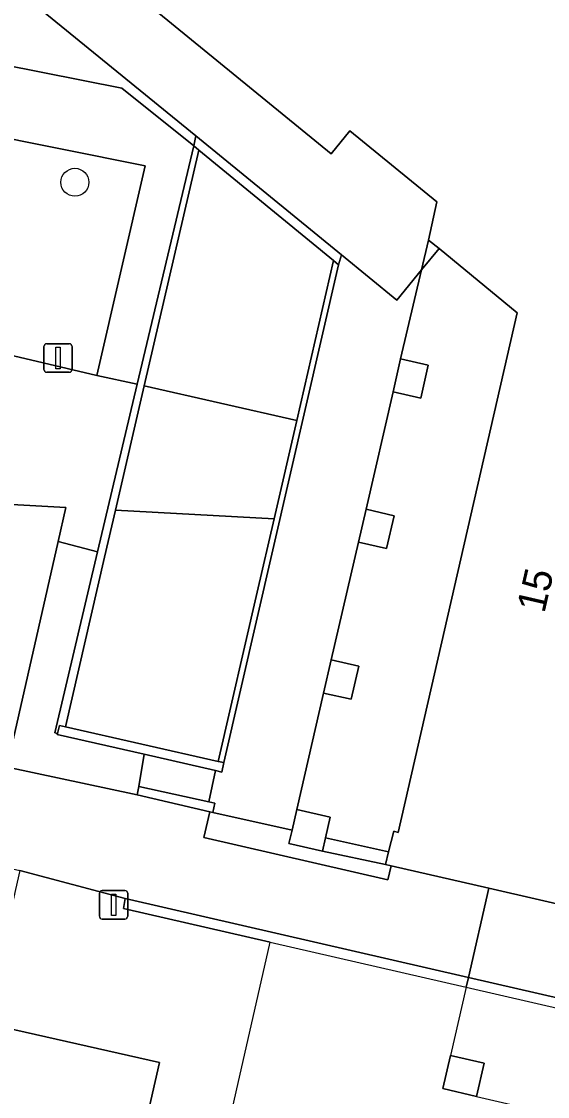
# Model space of a CAD drawing. Extents: x 161772 to 163126, y 383092 to 383917.
# Drawn here: x 161928.88 to 161947.28, y 383170.5 to 383208.09 of the extents above; entities that cross this region are included whole.
import ezdxf

# ---------------------------------------------------------------- set-up
doc = ezdxf.new("R2010")
doc.units = 0
for name, color, linetype in [('IMGEO_Boom', 7, 'Continuous'), ('IMGEO_Groenvoorziening', 7, 'Continuous'), ('IMGEO_Kademuur', 7, 'Continuous'), ('IMGEO_Lichtmast', 7, 'Continuous'), ('IMGEO_Pand', 7, 'Continuous'), ('IMGEO_Pand_nummerreeks', 7, 'Continuous'), ('IMGEO_Pand_overbouw', 7, 'Continuous'), ('IMGEO_Voetpad_gesloten', 7, 'Continuous'), ('IMGEO_Voetpad_op_trap', 7, 'Continuous'), ('IMGEO_Voetpad_open', 7, 'Continuous'), ('IMGEO_Waterloop', 7, 'Continuous')]:
    doc.layers.add(name, color=color, linetype=linetype)

msp = doc.modelspace()

# ---------------------------------------------------------------- linework, layer by layer
at = {"layer": 'IMGEO_Boom'}
msp.add_circle((161930.751, 383202.465), 0.489, dxfattribs=at)
at = {"layer": 'IMGEO_Groenvoorziening'}
for points in [[(161921.974, 383214.686), (161917.042, 383208.794), (161932.393, 383205.759), (161934.908, 383203.737), (161934.979, 383204.092)], [(161933.179, 383195.343), (161938.512, 383194.138), (161939.8, 383199.726), (161935.087, 383203.59)], [(161937.128, 383188.136), (161937.719, 383190.697), (161932.174, 383191), (161931.793, 383189.355), (161930.42, 383183.422), (161935.764, 383182.216)]]:
    msp.add_lwpolyline(points, close=True, dxfattribs=at)
for points in [[(161924.643, 383197.335), (161931.516, 383195.707), (161933.211, 383203.037), (161915.433, 383206.604), (161910.516, 383200.666), (161915.113, 383199.56)], [(161913.737, 383193.709), (161906.322, 383195.46), (161900.634, 383188.537), (161928.424, 383182.206), (161930.17, 383189.903), (161930.44, 383191.095), (161923.279, 383191.486)]]:
    msp.add_lwpolyline(points, dxfattribs=at)
at = {"layer": 'IMGEO_Kademuur'}
for points in [[(161932.509, 383177.423), (161932.457, 383177.072), (161937.581, 383175.895), (161944.437, 383174.32), (161944.517, 383174.665)], [(161944.517, 383174.665), (161944.437, 383174.32), (161982.458, 383165.585), (161982.538, 383165.93)]]:
    msp.add_lwpolyline(points, close=True, dxfattribs=at)
at = {"layer": 'IMGEO_Lichtmast'}
for p, q in [((161929.667, 383195.921), (161929.667, 383196.721)), ((161929.667, 383196.721), (161929.667, 383195.921)), ((161929.767, 383196.821), (161930.557, 383196.821)), ((161930.557, 383196.821), (161929.767, 383196.821)), ((161930.657, 383196.721), (161930.657, 383195.921)), ((161930.657, 383195.921), (161930.657, 383196.721)), ((161930.557, 383195.821), (161929.767, 383195.821)), ((161929.767, 383195.821), (161930.557, 383195.821)), ((161931.609, 383176.803), (161931.609, 383177.603)), ((161931.609, 383177.603), (161931.609, 383176.803)), ((161931.709, 383177.703), (161932.499, 383177.703)), ((161932.499, 383177.703), (161931.709, 383177.703)), ((161932.599, 383177.603), (161932.599, 383176.803)), ((161932.599, 383176.803), (161932.599, 383177.603)), ((161932.499, 383176.703), (161931.709, 383176.703)), ((161931.709, 383176.703), (161932.499, 383176.703))]:
    msp.add_line(p, q, dxfattribs=at)
for points in [[(161930.087, 383196.696), (161930.237, 383196.696), (161930.237, 383195.946), (161930.087, 383195.946), (161930.087, 383196.696)], [(161932.029, 383177.578), (161932.179, 383177.578), (161932.179, 383176.828), (161932.029, 383176.828), (161932.029, 383177.578)]]:
    msp.add_lwpolyline(points, dxfattribs=at)
for centre, start, end in [((161929.767, 383196.721), 90, 180), ((161929.767, 383196.721), 90, 180), ((161930.557, 383196.721), 0, 90), ((161930.557, 383196.721), 360, 90), ((161929.767, 383195.921), 180, 270), ((161929.767, 383195.921), 180, 270), ((161930.557, 383195.921), 270, 0), ((161930.557, 383195.921), 270, 0), ((161931.709, 383177.603), 90, 180), ((161931.709, 383177.603), 90, 180), ((161932.499, 383177.603), 0, 90), ((161932.499, 383177.603), 360, 90), ((161931.709, 383176.803), 180, 270), ((161931.709, 383176.803), 180, 270), ((161932.499, 383176.803), 270, 0), ((161932.499, 383176.803), 270, 0)]:
    msp.add_arc(centre, 0.1, start, end, dxfattribs=at)
at = {"layer": 'IMGEO_Pand'}
msp.add_lwpolyline([(161905.311, 383231.535), (161939.716, 383203.459), (161940.372, 383204.262), (161943.413, 383201.779), (161943.126, 383200.444), (161943.49, 383200.144), (161946.22, 383197.897), (161942.062, 383179.735), (161941.903, 383179.773), (161941.727, 383179.058), (161941.617, 383178.612), (161941.818, 383178.566), (161945.234, 383177.78), (161983.253, 383169.032)], dxfattribs=at)
for points in [[(161943.114, 383196.069), (161942.147, 383196.292), (161941.882, 383195.142), (161942.849, 383194.919)], [(161941.916, 383190.806), (161940.938, 383191.031), (161940.674, 383189.884), (161941.653, 383189.659)], [(161940.68, 383185.551), (161939.722, 383185.771), (161939.454, 383184.607), (161940.413, 383184.387)], [(161939.681, 383180.262), (161938.512, 383180.531), (161938.347, 383179.812), (161938.24, 383179.349), (161939.409, 383179.08), (161939.516, 383179.544)], [(161945.063, 383171.659), (161943.887, 383171.93), (161943.621, 383170.773), (161944.797, 383170.503)]]:
    msp.add_lwpolyline(points, close=True, dxfattribs=at)
at = {"layer": 'IMGEO_Pand_overbouw'}
msp.add_lwpolyline([(161939.409, 383179.08), (161941.617, 383178.612), (161941.727, 383179.058), (161941.903, 383179.773), (161942.062, 383179.735), (161946.22, 383197.897), (161943.49, 383200.144), (161943.126, 383200.444), (161942.88, 383199.401), (161942.147, 383196.292), (161943.114, 383196.069), (161942.849, 383194.919), (161941.882, 383195.142), (161940.938, 383191.031), (161941.916, 383190.806), (161941.653, 383189.659), (161940.674, 383189.884), (161939.722, 383185.771), (161940.68, 383185.551), (161940.413, 383184.387), (161939.454, 383184.607), (161938.512, 383180.531), (161939.681, 383180.262), (161939.516, 383179.544)], close=True, dxfattribs=at)
msp.add_lwpolyline([(161983.253, 383169.032), (161945.234, 383177.78), (161944.517, 383174.665), (161944.437, 383174.32), (161943.887, 383171.93), (161945.063, 383171.659), (161944.797, 383170.503), (161948.896, 383169.557)], dxfattribs=at)
at = {"layer": 'IMGEO_Voetpad_gesloten'}
msp.add_lwpolyline([(161901.812, 383231.182), (161913.633, 383221.52), (161915.063, 383220.352), (161918.785, 383217.291), (161920.904, 383215.558), (161921.974, 383214.686), (161934.979, 383204.092), (161940.08, 383199.924), (161942.01, 383198.341), (161942.88, 383199.401), (161943.126, 383200.444), (161943.413, 383201.779), (161940.372, 383204.262), (161939.716, 383203.459), (161905.311, 383231.535)], dxfattribs=at)
for points in [[(161934.908, 383203.737), (161935.087, 383203.59), (161939.8, 383199.726), (161939.979, 383199.579), (161940.08, 383199.924), (161934.979, 383204.092)], [(161933.179, 383195.343), (161935.087, 383203.59), (161934.908, 383203.737), (161932.925, 383195.401), (161931.539, 383189.54), (161930.045, 383183.211), (161930.139, 383183.188), (161930.212, 383183.469), (161930.42, 383183.422), (161931.793, 383189.355), (161932.174, 383191)], [(161943.126, 383200.444), (161942.88, 383199.401), (161943.49, 383200.144)], [(161939.516, 383179.544), (161941.727, 383179.058), (161941.903, 383179.773), (161942.062, 383179.735), (161946.22, 383197.897), (161943.49, 383200.144), (161942.88, 383199.401), (161942.147, 383196.292), (161943.114, 383196.069), (161942.849, 383194.919), (161941.882, 383195.142), (161940.938, 383191.031), (161941.916, 383190.806), (161941.653, 383189.659), (161940.674, 383189.884), (161939.722, 383185.771), (161940.68, 383185.551), (161940.413, 383184.387), (161939.454, 383184.607), (161938.512, 383180.531), (161939.681, 383180.262)], [(161939.979, 383199.579), (161939.8, 383199.726), (161938.512, 383194.138), (161937.719, 383190.697), (161937.128, 383188.136), (161935.764, 383182.216), (161935.961, 383182.174)], [(161935.266, 383179.559), (161935.474, 383180.458), (161932.928, 383181.042), (161898.656, 383188.359), (161896.493, 383185.753), (161896.762, 383185.692), (161900.61, 383184.813), (161928.824, 383178.397), (161932.509, 383177.423), (161944.517, 383174.665), (161945.234, 383177.78), (161941.818, 383178.566), (161941.702, 383178.07)], [(161933.178, 383182.464), (161935.675, 383181.895), (161935.895, 383181.845), (161935.961, 383182.174), (161935.764, 383182.216), (161930.42, 383183.422), (161930.212, 383183.469), (161930.139, 383183.188), (161930.131, 383183.158)], [(161932.988, 383181.34), (161932.928, 383181.042), (161935.474, 383180.458), (161935.578, 383180.434), (161935.643, 383180.758), (161935.442, 383180.802)], [(161935.266, 383179.559), (161941.702, 383178.07), (161941.818, 383178.566), (161941.617, 383178.612), (161939.409, 383179.08), (161938.24, 383179.349), (161938.347, 383179.812), (161935.578, 383180.434), (161935.474, 383180.458)], [(161939.409, 383179.08), (161941.617, 383178.612), (161941.727, 383179.058), (161939.516, 383179.544)]]:
    msp.add_lwpolyline(points, close=True, dxfattribs=at)
at = {"layer": 'IMGEO_Voetpad_op_trap'}
msp.add_lwpolyline([(161938.512, 383194.138), (161933.179, 383195.343), (161932.174, 383191), (161937.719, 383190.697)], close=True, dxfattribs=at)
at = {"layer": 'IMGEO_Voetpad_open'}
for points in [[(161919.991, 383214.466), (161919.775, 383214.193), (161919.918, 383214.063), (161909.282, 383200.947), (161910.516, 383200.666), (161915.433, 383206.604), (161933.211, 383203.037), (161931.516, 383195.707), (161932.925, 383195.401), (161934.908, 383203.737), (161932.393, 383205.759), (161917.042, 383208.794), (161921.974, 383214.686), (161920.904, 383215.558), (161920.718, 383215.321), (161920.546, 383215.462), (161919.83, 383214.597)], [(161935.675, 383181.895), (161935.442, 383180.802), (161935.643, 383180.758), (161935.578, 383180.434), (161938.347, 383179.812), (161938.512, 383180.531), (161939.454, 383184.607), (161939.722, 383185.771), (161940.674, 383189.884), (161940.938, 383191.031), (161941.882, 383195.142), (161942.147, 383196.292), (161942.88, 383199.401), (161942.01, 383198.341), (161940.08, 383199.924), (161939.979, 383199.579), (161935.961, 383182.174), (161935.895, 383181.845)], [(161932.928, 383181.042), (161932.988, 383181.34), (161933.178, 383182.464), (161930.131, 383183.158), (161930.139, 383183.188), (161930.045, 383183.211), (161931.539, 383189.54), (161930.17, 383189.903), (161928.424, 383182.206), (161900.634, 383188.537), (161906.322, 383195.46), (161905.083, 383195.774), (161899.241, 383188.593), (161898.889, 383188.662), (161898.656, 383188.359)], [(161933.178, 383182.464), (161932.988, 383181.34), (161935.442, 383180.802), (161935.675, 383181.895)], [(161932.831, 383154.966), (161937.581, 383175.895), (161932.457, 383177.072), (161932.509, 383177.423), (161928.824, 383178.397), (161928.677, 383177.741), (161928.103, 383175.177), (161926.468, 383173.314), (161933.708, 383171.683), (161930.061, 383155.701), (161930.061, 383155.701)], [(161983.253, 383169.032), (161945.234, 383177.78), (161944.517, 383174.665), (161982.538, 383165.93)], [(161914.888, 383159.724), (161930.061, 383155.701), (161930.061, 383155.701), (161933.708, 383171.683), (161926.468, 383173.314)]]:
    msp.add_lwpolyline(points, close=True, dxfattribs=at)
for points in [[(161931.516, 383195.707), (161924.643, 383197.335)], [(161923.279, 383191.486), (161930.44, 383191.095), (161930.17, 383189.903), (161931.539, 383189.54), (161932.925, 383195.401), (161931.516, 383195.707)]]:
    msp.add_lwpolyline(points, dxfattribs=at)
at = {"layer": 'IMGEO_Waterloop'}
msp.add_lwpolyline([(161932.831, 383154.966), (161937.581, 383175.895), (161944.437, 383174.32), (161982.458, 383165.585), (161990.33, 383163.776), (161986.972, 383149.331), (162000, 383145.804), (162029.115, 383137.922), (162112.481, 383115.352), (162139.881, 383107.934), (162162.911, 383101.699), (162162.56, 383099.901), (162165.814, 383099.192), (162166.809, 383098.975), (162168.602, 383098.586), (162174.82, 383097.237), (162174.82, 383097.237), (162171.611, 383091.655), (162047.886, 383124.46), (162039.073, 383130.851), (162037.424, 383128.677), (162040.518, 383126.413), (162002.94, 383136.377), (161932.831, 383154.966)], dxfattribs=at)
msp.add_lwpolyline([(161944.797, 383170.503), (161943.621, 383170.773), (161943.887, 383171.93), (161945.063, 383171.659)], close=True, dxfattribs=at)

# ---------------------------------------------------------------- texts
at = {"layer": 'IMGEO_Pand_nummerreeks'}
msp.add_text('15', height=1, rotation=77.1029, dxfattribs=at).set_placement((161947.174, 383187.37))

doc.saveas('drawing.dxf')
